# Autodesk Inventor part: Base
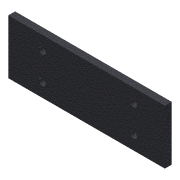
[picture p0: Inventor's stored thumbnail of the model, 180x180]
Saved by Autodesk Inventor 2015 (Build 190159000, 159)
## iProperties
Created: 2013-01
Part Number: Base
Material: Iron, Cast
Document SubType Name: Modeling
Designer: CADCIM
Density: 7.25 g/cm^3
Appearance: Iron - Cast
Mass: 163.903 g
Surface Area: 109.071 cm^2
Volume: 22.6073 cm^3
Author: CADCIM
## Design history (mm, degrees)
sketch "Sketch1"
  geometry: L1 (57.5, -20)-(-57.5, -20); L2 (-57.5, -20)-(-57.5, 20); L3 (-57.5, 20)-(57.5, 20); L4 (57.5, 20)-(57.5, -20); 1 further point
  constraints: 8 end point, 2 parallel, 1 horizontal, 1 perpendicular
  dimensions: "d0" = 115 distance of L1.start L1.end; "d2" = 40 distance of L3.end L1.start; "d3" = 57.5 distance from line of point (0, 0) L4; "d4" = 20 distance from line of point (0, 0) L1
extrude "Extrusion1" new body sketch "Sketch1" distance "d5" = 5; taper "d6" = 0 deg
hole "Hole2" diameter "d18" = 5; stored, may be unused: countersink angle "d22" = 90 deg, drill point angle "d24" = 118 deg; dims "d16" = 25, "d17" = 1, "d19" = 6, "d20" = 4, "d21" = 2, "d23" = 8
pattern_linear "Rectangular Pattern1" dims "d27" = 67
body "Solid1"
